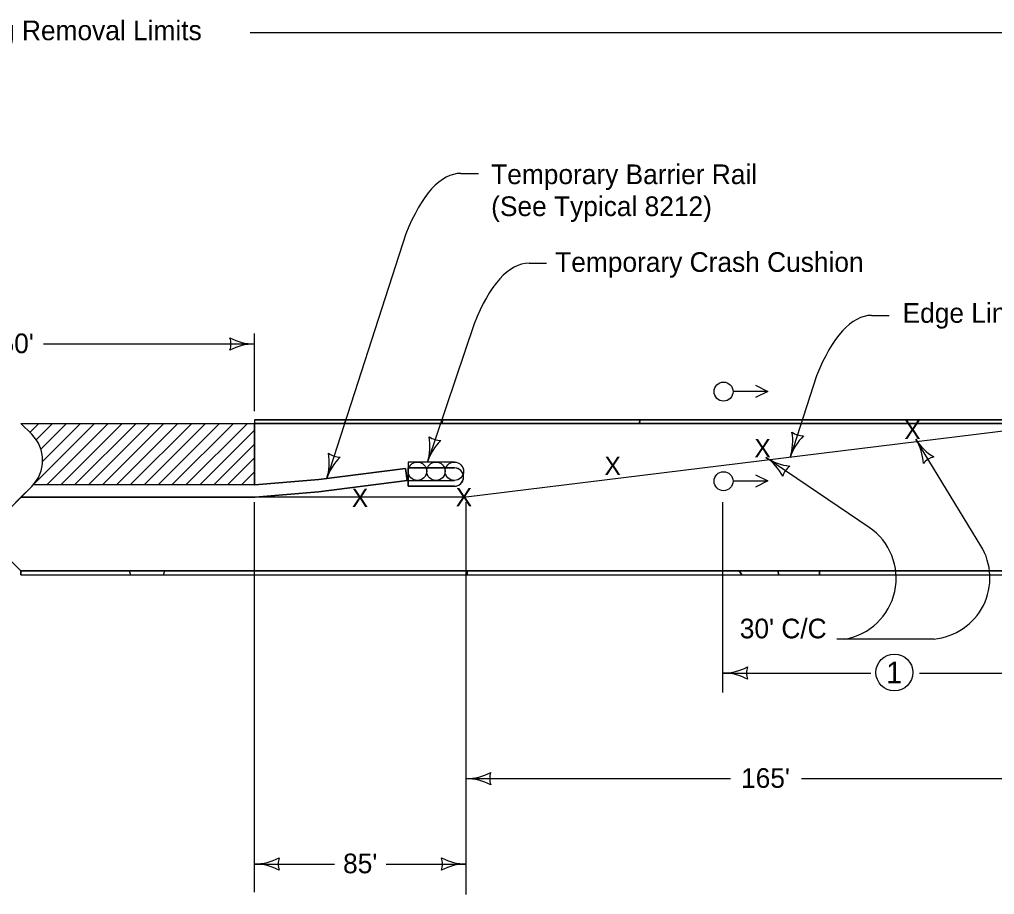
# Model space of a CAD drawing. Extents: x 10124 to 16850, y 7924 to 12166.
# Drawn here: x 15243 to 16036, y 9042 to 9753 of the extents above; entities that cross this region are included whole.
import ezdxf

# ---------------------------------------------------------------- set-up
doc = ezdxf.new("R2010")
doc.units = 0
for name, color, linetype in [('dsnCellElements', 7, 'Continuous'), ('dsnStdLineWork', 7, 'Continuous'), ('dsnStdShading', 7, 'Continuous'), ('Level 2', 7, 'Continuous')]:
    doc.layers.add(name, color=color, linetype=linetype)

msp = doc.modelspace()

# ---------------------------------------------------------------- linework, layer by layer
at = {"layer": 'dsnCellElements'}
for centre, radius, start, end in [((15829.65, 9410.29), 42.5, 342.08492, 10.15741), ((15881.05, 9431.13), 16.42, 234.35157, 269.81827), ((15534.51, 9406.53), 42.5, 342.08492, 10.15741), ((15615.39, 9380.39), 42.5, 134.01243, 162.08492), ((15585.91, 9427.37), 16.42, 234.35157, 269.81827), ((15910.53, 9384.14), 42.5, 134.01243, 162.08492), ((16008.59, 9434.18), 42.5, 211.39894, 239.47142), ((15936.03, 9389.9), 42.5, 3.32645, 31.39894), ((15452.6, 9393.04), 42.5, 342.08492, 10.15741), ((15504, 9413.87), 16.42, 234.35157, 269.81827), ((15533.48, 9366.89), 42.5, 134.01243, 162.08492), ((15874.2, 9432.39), 42.5, 235.83862, 263.91111), ((15826.47, 9362.06), 42.5, 27.76614, 55.83862), ((15990.87, 9381.62), 16.42, 103.66558, 139.13229), ((15879.82, 9377.22), 16.42, 128.10527, 163.57197), ((15606.41, 9178.35), 42.5, 270, 298.07249), ((15642.05, 9135.85), 16.42, 162.26665, 197.73335), ((15606.41, 9093.35), 42.5, 61.92751, 90), ((15434.27, 9108.85), 42.5, 270, 298.07249), ((15469.91, 9066.35), 16.42, 162.26665, 197.73335), ((15570.78, 9066.35), 16.42, 342.26665, 17.73335), ((15606.41, 9108.85), 42.5, 241.92751, 270), ((15434.27, 9023.85), 42.5, 61.92751, 90), ((15606.41, 9023.85), 42.5, 90, 118.07249)]:
    msp.add_arc(centre, radius, start, end, dxfattribs=at)
at = {"layer": 'dsnStdLineWork'}
for p, q in [((15434.27, 9427.79), (15434.27, 9424.79)), ((15434.27, 9427.79), (15434.27, 9424.79)), ((15508.49, 9427.79), (15434.27, 9427.79)), ((15434.27, 9424.79), (15434.97, 9424.79)), ((15434.97, 9424.79), (15507.52, 9424.79)), ((15508.49, 9427.79), (15507.52, 9424.79)), ((15507.52, 9424.79), (15508.49, 9427.79)), ((15507.52, 9424.79), (15586.61, 9424.79)), ((15587.58, 9427.79), (15508.49, 9427.79)), ((15587.58, 9427.79), (15586.61, 9424.79)), ((15586.61, 9424.79), (15587.58, 9427.79)), ((15586.61, 9424.79), (15747.08, 9424.79)), ((15748.05, 9427.79), (15587.58, 9427.79)), ((15748.05, 9427.79), (15747.08, 9424.79)), ((15747.08, 9424.79), (15748.05, 9427.79)), ((15747.08, 9424.79), (16040.03, 9424.79)), ((16061.71, 9427.79), (15748.05, 9427.79)), ((15244.27, 9301.79), (15244.27, 9304.79)), ((15244.27, 9304.79), (16746.73, 9304.79)), ((15244.27, 9304.79), (16746.73, 9304.79)), ((15332.38, 9304.79), (15244.27, 9304.79)), ((15244.27, 9304.79), (15244.27, 9301.79)), ((15361.2, 9304.79), (15332.38, 9304.79)), ((15607.23, 9304.79), (15361.2, 9304.79)), ((15607.23, 9301.79), (15607.23, 9304.79)), ((15828.57, 9304.79), (15607.23, 9304.79)), ((15607.23, 9304.79), (15607.23, 9301.79)), ((15830.74, 9301.79), (15828.57, 9304.79)), ((15828.57, 9304.79), (15830.74, 9301.79)), ((15860.39, 9304.79), (15828.57, 9304.79)), ((15860.53, 9301.79), (15860.39, 9304.79)), ((15893.78, 9304.79), (15860.39, 9304.79)), ((15860.39, 9304.79), (15860.53, 9301.79)), ((15893.78, 9301.79), (15893.78, 9304.79)), ((16167.67, 9304.79), (15893.78, 9304.79)), ((15893.78, 9304.79), (15893.78, 9301.79)), ((15244.27, 9301.79), (16746.73, 9301.79)), ((15244.27, 9301.79), (15333.33, 9301.79)), ((15333.33, 9301.79), (15360.25, 9301.79)), ((15360.25, 9301.79), (15607.23, 9301.79)), ((15607.23, 9301.79), (15830.74, 9301.79)), ((15830.74, 9301.79), (15860.53, 9301.79)), ((15860.53, 9301.79), (15893.78, 9301.79)), ((15893.78, 9301.79), (16166.66, 9301.79))]:
    msp.add_line(p, q, dxfattribs=at)
for points in [[(15434.27, 9427.79), (16746.73, 9427.79)], [(15434.27, 9424.79), (16746.73, 9424.79)], [(15434.97, 9424.79), (16747.43, 9424.79)]]:
    msp.add_lwpolyline(points, dxfattribs=at)
for start, end in [(191.32986, 203.61796), (191.32986, 203.61796), (336.38204, 348.67014), (336.38204, 348.67014)]:
    msp.add_arc((15346.79, 9307.67), 14.69, start, end, dxfattribs=at)
at = {"layer": 'dsnStdShading'}
for p, q in [((15596.84, 9388.7), (15559.33, 9388.7)), ((15559.33, 9388.7), (15559.33, 9373.7)), ((15559.33, 9373.7), (15596.84, 9373.7))]:
    msp.add_line(p, q, dxfattribs=at)
msp.add_arc((15596.84, 9381.2), 7.5, 270.00239, 89.99723, dxfattribs=at)
at = {"layer": 'Level 2'}
for p, q in [((15430.7, 9742.96), (16094.27, 9742.96)), ((15602.16, 9628.31), (15616.38, 9628.31)), ((15557.43, 9579.17), (15493.04, 9379.97)), ((15657.6, 9555.15), (15671.82, 9555.15)), ((15936.29, 9512.76), (15950.51, 9512.76)), ((15612.87, 9506.01), (15574.95, 9393.46)), ((15434.27, 9434.79), (15434.27, 9498.09)), ((15262.56, 9489.48), (15434.27, 9489.48)), ((15891.56, 9463.62), (15870.09, 9397.22)), ((15823.59, 9451.09), (15851.54, 9451.09)), ((15253.06, 9416), (15244.27, 9424.79)), ((15251.5, 9417.56), (15258.73, 9424.79)), ((15255.45, 9376.27), (15303.97, 9424.79)), ((15256.75, 9411.51), (15270.03, 9424.79)), ((15260.44, 9403.88), (15281.34, 9424.79)), ((15261.84, 9393.97), (15292.65, 9424.79)), ((15265.28, 9374.79), (15315.28, 9424.79)), ((15276.6, 9374.79), (15326.6, 9424.79)), ((15287.91, 9374.79), (15337.91, 9424.79)), ((15299.22, 9374.79), (15349.22, 9424.79)), ((15310.54, 9374.79), (15360.54, 9424.79)), ((15321.85, 9374.79), (15371.85, 9424.79)), ((15333.16, 9374.79), (15383.16, 9424.79)), ((15344.48, 9374.79), (15394.48, 9424.79)), ((15355.79, 9374.79), (15405.79, 9424.79)), ((15367.1, 9374.79), (15417.1, 9424.79)), ((15378.42, 9374.79), (15428.42, 9424.79)), ((15434.27, 9374.79), (15434.27, 9424.79)), ((16746.73, 9424.79), (15434.27, 9424.79)), ((15434.27, 9424.79), (15434.27, 9374.79)), ((16094.27, 9424.79), (15606.41, 9364.79)), ((15389.73, 9374.79), (15434.27, 9419.33)), ((15401.03, 9374.79), (15434.27, 9408.03)), ((16025.22, 9325.36), (15972.31, 9412.04)), ((15412.33, 9374.79), (15434.27, 9396.73)), ((15559.33, 9393.46), (15559.33, 9378.46)), ((15596.84, 9393.46), (15559.33, 9393.46)), ((15934.36, 9340.21), (15850.34, 9397.22)), ((15423.63, 9374.79), (15434.27, 9385.43)), ((15557.05, 9388.3), (15486.53, 9379.12)), ((15486.53, 9379.12), (15557.05, 9388.3)), ((15486.53, 9379.12), (15557.05, 9388.3)), ((15558.32, 9378.46), (15557.05, 9388.3)), ((15557.05, 9388.3), (15558.32, 9378.43)), ((15557.05, 9388.3), (15558.32, 9378.46)), ((15559.33, 9373.7), (15559.33, 9388.7)), ((15559.33, 9388.7), (15596.84, 9388.7)), ((15434.27, 9374.79), (15486.53, 9379.12)), ((15486.53, 9379.12), (15434.46, 9374.79)), ((15434.46, 9374.79), (15486.53, 9379.12)), ((15486.37, 9369.11), (15558.32, 9378.46)), ((15558.32, 9378.46), (15486.37, 9369.11)), ((15558.32, 9378.46), (15486.37, 9369.11)), ((15559.33, 9378.46), (15596.84, 9378.46)), ((15823.59, 9378.2), (15851.54, 9378.2)), ((15235.49, 9356), (15253.06, 9373.57)), ((15253.06, 9373.57), (15244.27, 9364.79)), ((15434.46, 9374.79), (15254.27, 9374.79)), ((15434.46, 9374.79), (15254.27, 9374.79)), ((15434.81, 9364.79), (15486.37, 9369.11)), ((15486.37, 9369.11), (15434.81, 9364.79)), ((15486.37, 9369.11), (15434.81, 9364.79)), ((15596.84, 9373.7), (15559.33, 9373.7)), ((15244.27, 9364.79), (15434.81, 9364.79)), ((15434.81, 9364.79), (15244.27, 9364.79)), ((15434.81, 9364.79), (15244.27, 9364.79)), ((15434.27, 9043.48), (15434.27, 9360.69)), ((15606.41, 9364.79), (15434.81, 9364.79)), ((15606.41, 9041.56), (15606.41, 9360.69)), ((15815.36, 9205.81), (15815.36, 9360.69)), ((15244.27, 9304.79), (15235.49, 9313.57)), ((15235.49, 9313.57), (15244.27, 9304.79)), ((15244.27, 9304.79), (16746.73, 9304.79)), ((15987.09, 9249.44), (15908.03, 9249.44)), ((15815.36, 9221.71), (15935.73, 9221.71)), ((15975.18, 9221.71), (16094.27, 9221.71)), ((15606.41, 9135.85), (15821.41, 9135.85)), ((15879.27, 9135.85), (16094.27, 9135.85)), ((15434.27, 9066.35), (15499.27, 9066.35)), ((15541.41, 9066.35), (15606.41, 9066.35))]:
    msp.add_line(p, q, dxfattribs=at)
for points in [[(15841.91, 9455.91), (15851.91, 9450.91), (15841.91, 9445.91)], [(15244.27, 9424.79), (15434.27, 9424.79)], [(15841.91, 9383.02), (15851.91, 9378.02), (15841.91, 9373.02)], [(15254.27, 9374.79), (15254.24, 9374.82)], [(15244.27, 9364.79), (15244.27, 9364.79), (15235.49, 9356)]]:
    msp.add_lwpolyline(points, dxfattribs=at)
for centre, radius in [((15815.86, 9450.73), 7.74), ((15566.83, 9385.96), 7.5), ((15566.83, 9385.96), 7.5), ((15581.84, 9385.96), 7.5), ((15581.84, 9385.96), 7.5), ((15596.84, 9385.96), 7.5), ((15596.84, 9385.96), 7.5), ((15815.86, 9377.84), 7.74), ((15954.82, 9222.21), 15)]:
    msp.add_circle(centre, radius, dxfattribs=at)
for centre, radius, start, end in [((15398.64, 9489.48), 16.42, 342.26665, 17.73335), ((15434.27, 9531.98), 42.5, 241.92751, 270), ((15434.27, 9446.98), 42.5, 90, 118.07249), ((15231.85, 9394.79), 30, 315, 45), ((15596.84, 9381.2), 7.5, 269.99962, 90), ((15231.85, 9394.79), 30, 315, 318.27125), ((15906.25, 9298.79), 50.05, 279.6171, 55.83863), ((15982.49, 9299.28), 50.05, 275.26461, 31.39894), ((15815.36, 9264.21), 42.5, 270, 298.07249), ((15851, 9221.71), 16.42, 162.26665, 197.73335), ((15815.36, 9179.21), 42.5, 61.92751, 90)]:
    msp.add_arc(centre, radius, start, end, dxfattribs=at)
for centre in [(15602.16, 9415.37), (15657.6, 9342.22), (15936.29, 9299.82)]:
    msp.add_ellipse(centre, major_axis=(0, 212.93), ratio=0.328743, start_param=0, end_param=0.693162, dxfattribs=at)

# ---------------------------------------------------------------- texts
for s, height, p in [('Pavement Marking Removal Limits', 16, (15060.75, 9736.64)), ('Temporary Barrier Rail', 16, (15626.79, 9619.55)), ('(See Typical 8212)', 16, (15626.79, 9593.55)), ('Temporary Crash Cushion', 16, (15678.89, 9548.16)), ('Edge Line', 16, (15961.51, 9506.72)), ("150'", 16, (15214.94, 9481.98)), ('X', 15, (15962.88, 9412.04)), ('X', 15, (15840.91, 9397.22)), ('X', 15, (15718.95, 9382.85)), ('X', 15, (15513.41, 9356.74)), ('X', 15, (15597.95, 9357.33)), ("30' C/C", 16, (15829.06, 9249.99)), ('1', 17.5, (15948.08, 9213.46)), ("165'", 16, (15830.09, 9128.35)), ("85'", 16, (15506.31, 9058.85))]:
    msp.add_text(s, height=height, dxfattribs=at).set_placement(p)

doc.saveas('drawing.dxf')
